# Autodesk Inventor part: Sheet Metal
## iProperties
Author: CM
Shininess: 64.0
Angle Display Precision: 2
Document Length Units: 11272
Document Angle Units: 11286
Document Time Units: 11279
Document Mass Units: 11290
Document Length Units Precision: 3
Document Angle Units Precision: 2
Compacted: True
PropertySet Name: _Private Model Information
Part Number: Sheet Metal
Material: Aluminum-6061
Document SubType Name: Sheet Metal
Designer: CM
Control State: 0
Master: False
Checked Out: False
PropertySet Name: Design Tracking Control
Density: 0.0
Volumn: 0.0
Area: 0.0
PropertySet Name: Model Information
